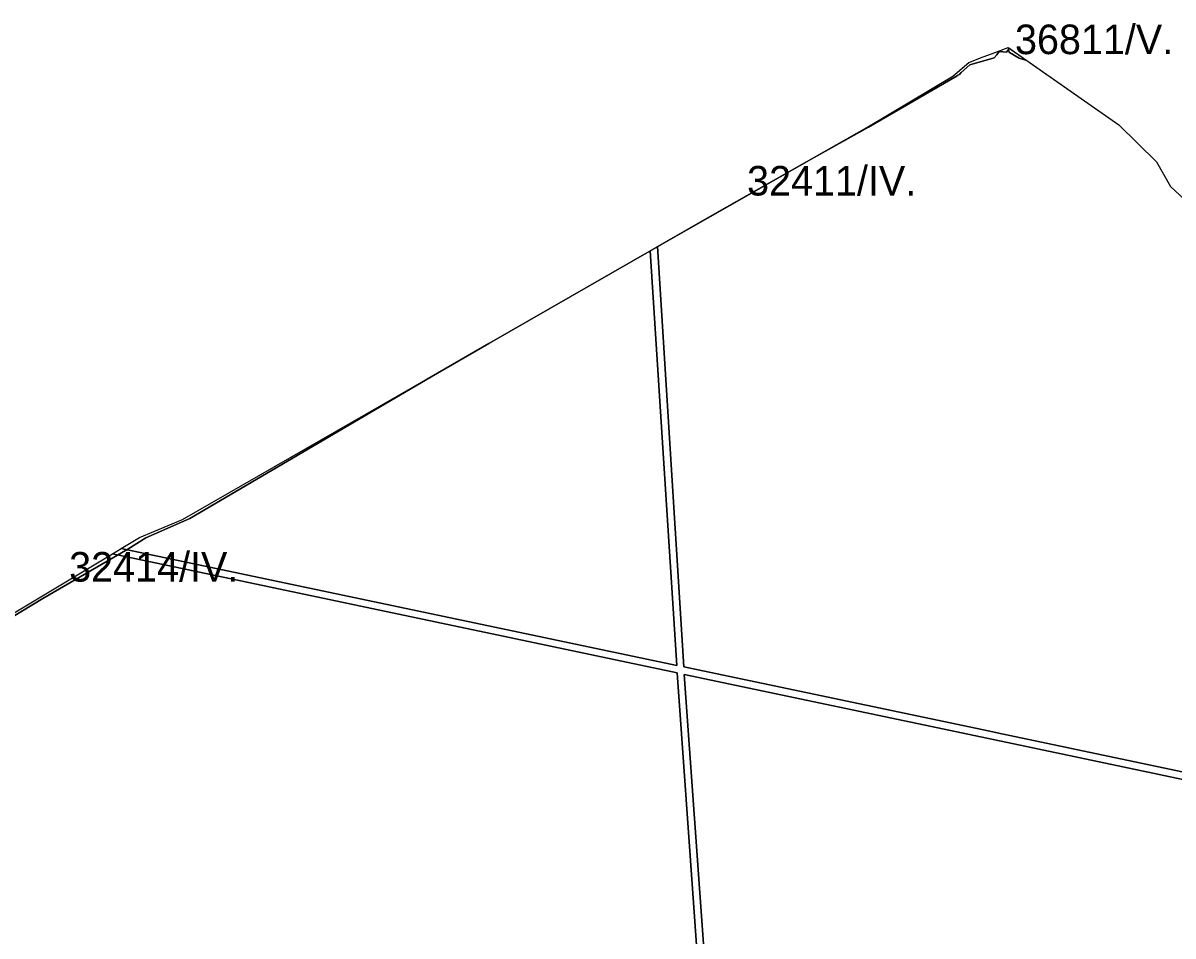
# Model space of a CAD drawing. Extents: x -535894 to -532827, y -1165802 to -1163635.
# Drawn here: x -535071 to -534487, y -1164098 to -1163635 of the extents above; entities that cross this region are included whole.
import ezdxf

# ---------------------------------------------------------------- set-up
doc = ezdxf.new("R2010")
doc.units = 0
doc.layers.add('BPEJ_s', color=7, linetype='Continuous')
doc.layers.add('PUPFL_s', color=7, linetype='Continuous')

msp = doc.modelspace()

# ---------------------------------------------------------------- linework, layer by layer
at = {"layer": 'BPEJ_s'}
for points in [[(-535123.09, -1163964.15), (-535060.95, -1163926.6), (-535017.814, -1163901.521), (-535008.66, -1163895.82), (-534986.45, -1163886.01), (-534863.837, -1163813.99), (-534863.824, -1163813.983), (-534834.57, -1163797.178), (-534752.117, -1163749.813), (-534748.506, -1163747.74), (-534733.08, -1163738.88), (-534669.42, -1163702.738), (-534641.998, -1163687.404), (-534596.99, -1163661.322), (-534596.89, -1163661.239), (-534595.689, -1163660.58), (-534594.955, -1163659.625), (-534590.404, -1163655.831), (-534578.054, -1163652.262), (-534576.833, -1163650.635), (-534575.583, -1163648.967), (-534571.892, -1163649.356), (-534570.875, -1163648)], [(-534570.875, -1163648), (-534570.594, -1163649.492), (-534570.37, -1163649.516), (-534565.465, -1163652.41), (-534561.475, -1163653.571), (-534514.86, -1163686.14), (-534495.67, -1163705.05), (-534488.62, -1163717.48), (-534476.78, -1163728.4)], [(-535193.05, -1164004.23), (-535025.69, -1163903.86), (-535021.19, -1163901.16), (-535011.93, -1163895.61), (-534990.07, -1163886.45), (-534834.589, -1163797.128), (-534834.57, -1163797.178), (-534863.824, -1163813.983), (-534863.837, -1163813.99), (-534986.45, -1163886.01), (-535008.66, -1163895.82), (-535017.814, -1163901.521), (-535060.95, -1163926.6), (-535123.09, -1163964.15)]]:
    msp.add_lwpolyline(points, dxfattribs=at)
for points in [[(-534570.772, -1163647.075), (-534570.875, -1163648), (-534571.892, -1163649.356), (-534575.583, -1163648.967), (-534576.833, -1163650.635), (-534578.054, -1163652.262), (-534590.404, -1163655.831), (-534594.955, -1163659.625), (-534595.689, -1163660.58), (-534596.89, -1163661.239), (-534596.99, -1163661.322), (-534641.998, -1163687.404), (-534669.42, -1163702.738), (-534733.08, -1163738.88), (-534748.506, -1163747.74), (-534752.117, -1163749.813), (-534834.57, -1163797.178), (-534834.589, -1163797.128), (-534752.66, -1163750.06), (-534749.05, -1163747.99), (-534718.97, -1163730.71), (-534642.84, -1163687.62), (-534599.15, -1163661.49), (-534591.03, -1163654.51), (-534583.72, -1163651.75), (-534579.5, -1163650.15), (-534570.98, -1163646.93)], [(-534561.475, -1163653.571), (-534565.465, -1163652.41), (-534570.37, -1163649.516), (-534570.594, -1163649.492), (-534570.875, -1163648), (-534570.772, -1163647.075)]]:
    msp.add_lwpolyline(points, close=True, dxfattribs=at)
at = {"layer": 'PUPFL_s'}
for points in [[(-534579.5, -1163650.15), (-534570.98, -1163646.93), (-534514.86, -1163686.14), (-534495.67, -1163705.05), (-534488.62, -1163717.48), (-534476.78, -1163728.4), (-534459.7, -1163738.33), (-534445.87, -1163741.61), (-534431.31, -1163750.05), (-534428.93, -1164025.8), (-534576.69, -1163994.7), (-534580.33, -1163993.93), (-534735.68, -1163961.24), (-534749.05, -1163747.99), (-534718.97, -1163730.71), (-534642.84, -1163687.62), (-534599.15, -1163661.49), (-534591.03, -1163654.51), (-534583.72, -1163651.75)], [(-534752.66, -1163750.06), (-534739.26, -1163960.49), (-535021.19, -1163901.16), (-535011.93, -1163895.61), (-534990.07, -1163886.45)], [(-534735.42, -1163965.07), (-534580.94, -1163997.64), (-534577.82, -1163998.3), (-534429.37, -1164029.61), (-534426.3, -1164271.96), (-534439.05, -1164259.47), (-534446.52, -1164256.91), (-534458.72, -1164249.64), (-534465.85, -1164242.8), (-534477.05, -1164227.75), (-534492.39, -1164221.02), (-534521.68, -1164205.56), (-534554.26, -1164192.45), (-534591.23, -1164182.82), (-534594.62, -1164181.93), (-534604.82, -1164180.29), (-534627.51, -1164173.48), (-534643.92, -1164165.11), (-534663.32, -1164170.6), (-534682.2, -1164171.34), (-534689.58, -1164178.65), (-534705.88, -1164181.51), (-534719.55, -1164186.71)]]:
    msp.add_lwpolyline(points, close=True, dxfattribs=at)
for points in [[(-534429.37, -1164029.61), (-534577.82, -1163998.3), (-534580.94, -1163997.64), (-534735.42, -1163965.07), (-534719.55, -1164186.71), (-534723.07, -1164188.05), (-534739, -1163964.32), (-535025.69, -1163903.86), (-535021.19, -1163901.16), (-534739.26, -1163960.49), (-534752.66, -1163750.06), (-534749.05, -1163747.99), (-534735.68, -1163961.24), (-534580.33, -1163993.93), (-534576.69, -1163994.7), (-534428.93, -1164025.8)], [(-535193.05, -1164004.23), (-535025.69, -1163903.86), (-534739, -1163964.32), (-534723.07, -1164188.05), (-534730.44, -1164190.85), (-534748.83, -1164193.12), (-534781.14, -1164187.86), (-534780.04, -1164184.13), (-534779.41, -1164181.96), (-534833.11, -1164171.65), (-534856.69, -1164168.25), (-534859.37, -1164167.86), (-534900.73, -1164174.23), (-534917.74, -1164173.57), (-534951.85, -1164167.07), (-534993.44, -1164171.93), (-534993.22, -1164184.39), (-534995, -1164182.89), (-535007.7, -1164178.2), (-535037.17, -1164175.56), (-535077.79, -1164162.19)]]:
    msp.add_lwpolyline(points, dxfattribs=at)

# ---------------------------------------------------------------- texts
at = {"layer": 'BPEJ_s'}
for s, p in [('36811/V.', (-534567.563, -1163650.323)), ('32411/IV.', (-534703.56, -1163722.054)), ('32414/IV.', (-535047.649, -1163917.962))]:
    msp.add_text(s, height=15, dxfattribs=at).set_placement(p)

doc.saveas('drawing.dxf')
